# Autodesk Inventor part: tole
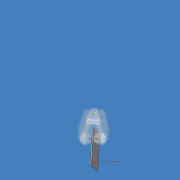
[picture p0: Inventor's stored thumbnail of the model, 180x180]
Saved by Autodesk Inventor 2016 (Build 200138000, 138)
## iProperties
Shininess: 64.0
Length Units: 11269
Angle Units: 11279
Time Units: 11290
Mass Units: 11283
Length Display Precision: 3
Angle Display Precision: 2
Compacted: True
Part Number: tole
Document SubType Name: Sheet Metal
Created: 2003-07
Material: Acier doux
Designer: trameau
Mass: 93600 g
Density: 7.86 g/cm^3
Sheet Metal Rule: Par défaut
Appearance: Métal - Acier
Density: 0.0
Volumn: 0.0
Area: 0.0
PropertySet Name: Model Information
Control State: 0
Master: False
Checked Out: False
Author: trameau
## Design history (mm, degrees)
node "Face1"
  sketch "Esquisse1"
    geometry: L1 (-30.048, 127.328)-(69.952, 127.328); L2 (69.952, 127.328)-(69.952, -22.672); L3 (69.952, -22.672)-(-30.048, -22.672); L4 (-30.048, -22.672)-(-30.048, 127.328)
    constraints: 8 end point, 2 parallel, 1 horizontal, 1 perpendicular
    dimensions: "d0" = 100 distance between parallel lines of L2 L4; "d1" = 150 distance between parallel lines of L1 L3
node "Solide1"
node "Corps solides"
node "Corps surfaciques"
feature "Plaque1" dims "Epaisseur" = 4
other parameters: "RayonPliage" = 4 (= Epaisseur), "LargeurGrugeage" = 4 (= Epaisseur), "ProfondeurGrugeage" = 2 (= 0.5 x Epaisseur), "TailleGrugeage" = 16 (= 4 x Epaisseur), "SeamGap" = 0.01, "RestesMinimum" = 8 (= 2 x Epaisseur), "Rayondetransition" = 4 (= RayonPliage), "d2" = 4 (= RayonPliage), "TailleRayonJacobi" = 4 (= Epaisseur), "TailleJeu" = 4 (= Epaisseur)
